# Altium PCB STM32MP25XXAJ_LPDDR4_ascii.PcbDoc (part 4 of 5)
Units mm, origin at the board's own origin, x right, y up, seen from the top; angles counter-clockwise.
Board outline 172 x 137 mm, 4 copper layers (Top Layer, Signal Layer 1, Signal Layer 2, Bottom Layer), stack 1.614 mm thick; 188 components, 294 nets, 1141 pads, 872 vias.
Unrouted connection lines stored in the file: 13.
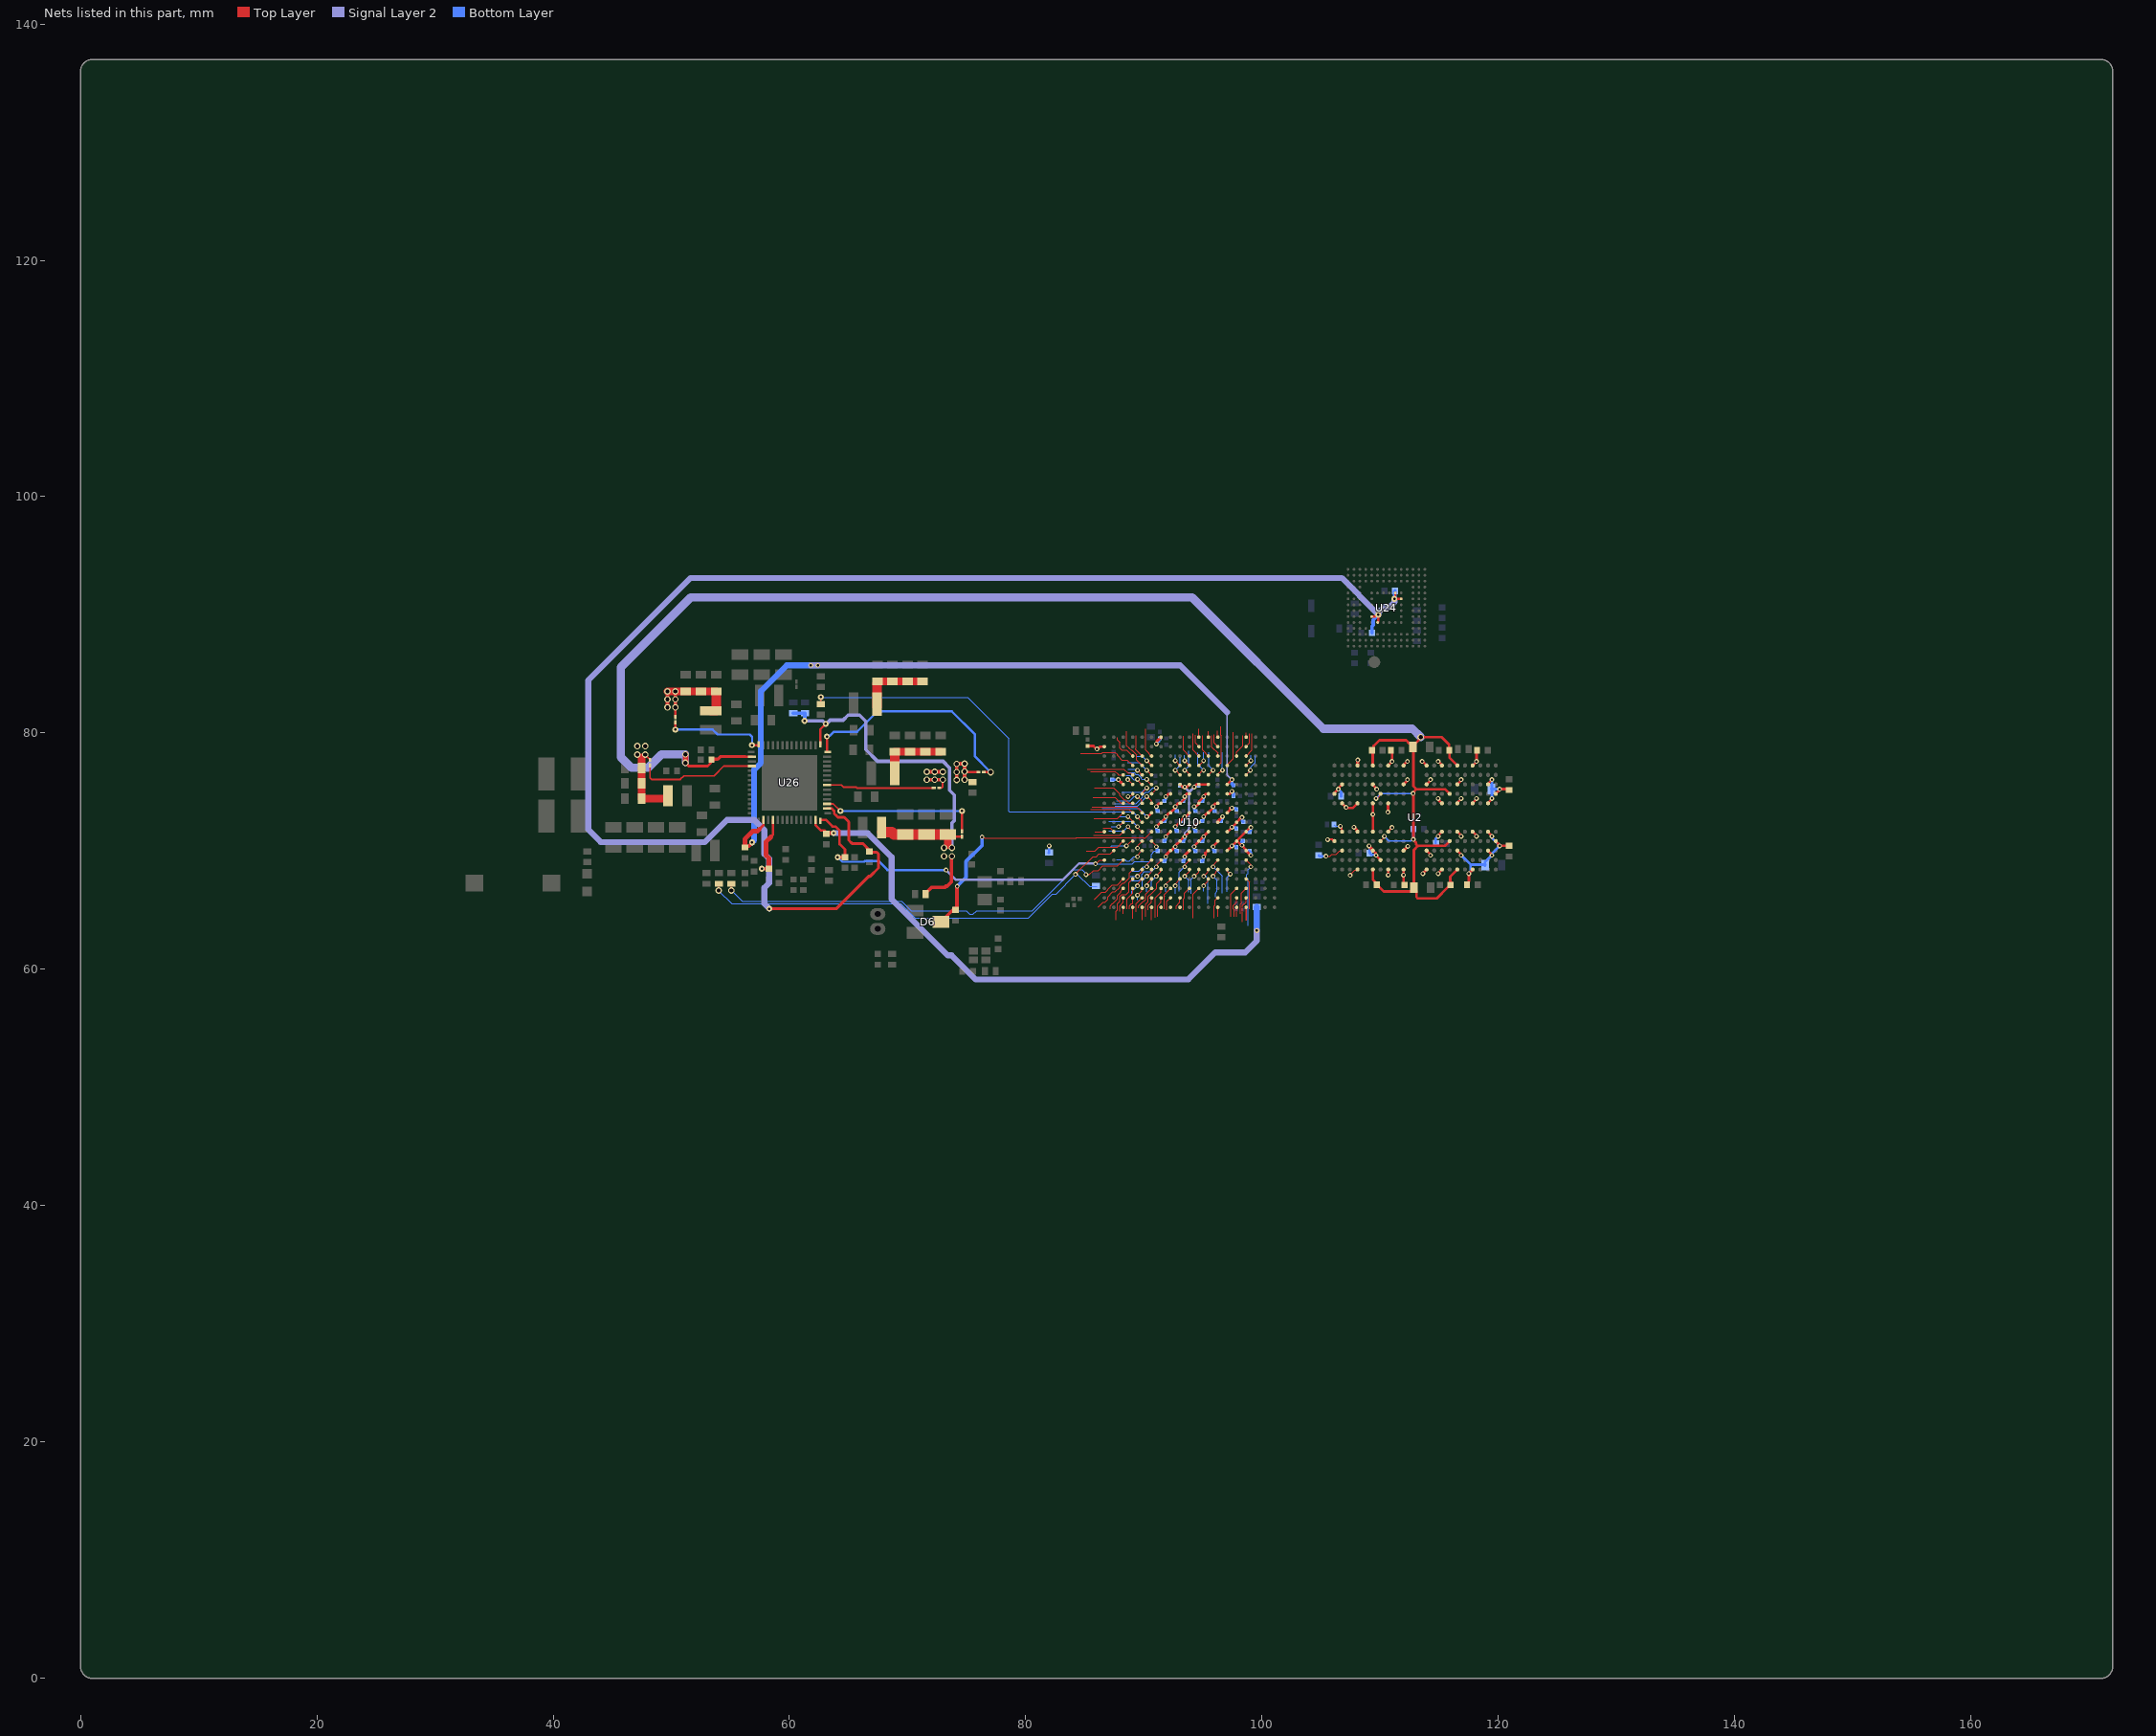
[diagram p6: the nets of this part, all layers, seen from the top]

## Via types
v1: diameter 0.55, hole 0.35, Top Layer to Bottom Layer, 349 vias
v2: diameter 0.4, hole 0.2, Top Layer to Bottom Layer, tented both sides, 257 vias
v3: diameter 0.5, hole 0.2, Top Layer to Bottom Layer, 189 vias
v4: diameter 0.4, hole 0.2, Top Layer to Bottom Layer, 77 vias

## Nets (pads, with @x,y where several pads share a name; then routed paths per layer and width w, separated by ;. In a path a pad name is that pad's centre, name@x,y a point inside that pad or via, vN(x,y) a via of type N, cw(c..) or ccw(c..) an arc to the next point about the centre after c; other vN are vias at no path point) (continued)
PB12: U10.B16 | length 1.2
  Top Layer w0.09: U10.B16@98.65,78.85 98.95,79.15 98.95,79.928
PB13: U10.C15 | length 1.9
  Top Layer w0.09: U10.C15@97.845,78.05 97.845,78.395 98.355,78.905 98.355,79.76
PB14: U10.E16 | length 1.9
  Top Layer w0.1: U10.E16@98.65,76.45 98.65,76.473 99.005,76.828 v2@99.005,76.85
  Bottom Layer w0.1: v2@99.005,76.85 99.062,76.907 99.062,77.157 99.408,77.503 99.408,78.078
  other v2: 99,76.85
PB15: U10.W3 | length 0.6
  Top Layer w0.09: 88.245,64.7 88.245,65.245 U10.W3@88.25,65.25
PC0: U10.P10 | length 2.9
  Top Layer w0.09: v2@93.428,68.775 93.428,68.804 93.845,69.221 U10.P10@93.845,69.25
  Bottom Layer w0.09: 93,66.609 93,68.215 93.45,68.665 v2(93.45,68.675)
PC1: U10.V9 | length 1
  Top Layer w0.09: 92.75,65.128 92.75,65.372 93.045,65.667 U10.V9@93.045,66.05
PC2: U10.V8 | length 1.1
  Top Layer w0.09: 91.945,65.05 91.945,65.75 U10.V8@92.245,66.05
PC3: U10.V5 | length 1.4
  Top Layer w0.09: 89.349,64.884 89.349,65.555 U10.V5@89.845,66.05
PC4: U10.T6 | length 1.1
  Top Layer w0.09: v2@90.283,67.201 90.283,67.242 90.645,67.603 U10.T6@90.645,67.65
  Bottom Layer w0.09: 90.25,66.569 v2(90.25,67.075)
PC5: U10.R7 | length 1.9
  Top Layer w0.09: v2(91.05,67.875) 91.426,68.251 91.426,68.426 U10.R7@91.45,68.45
  Bottom Layer w0.09: 90.633,66.839 90.633,67.453 v2@91.05,67.869
PC6: U10.T7 | length 3.7
  Top Layer w0.09: 90.165,64.471 90.165,65.532 90.344,65.711 90.344,66.17 90.518,66.345 90.562,66.345 91.084,66.867 91.084,67.243 91.445,67.603 U10.T7@91.445,67.65
PC7: U10.U6 | length 2.1
  Top Layer w0.09: 89.555,65.2 89.555,65.372 89.938,65.755 89.972,65.755 90.145,65.928 90.145,66.373 90.623,66.85 U10.U6@90.65,66.85
PC8: U10.V6 | length 1.1
  Top Layer w0.09: 90.355,65.038 90.355,65.389 90.65,65.684 U10.V6@90.65,66.05
PC9: U10.W6 | length 1.1
  Top Layer w0.09: 90.65,64.191 U10.W6@90.65,65.25
PC10: U10.U7 | length 2.7
  Top Layer w0.09: 90.96,64.366 90.96,66.03 91.45,66.521 U10.U7@91.45,66.85
PC11: U10.U5 | length 1.2
  Top Layer w0.09: v4(89.45,66.275) 89.826,66.651 89.826,66.826 U10.U5@89.85,66.85
  Bottom Layer w0.09: 89.448,65.866 89.45,65.868 v4(89.45,66.275)
PC12: U10.V4 | length 1.1
  Top Layer w0.09: 88.755,65.095 88.755,65.372 88.928,65.545 88.997,65.545 89.05,65.598 U10.V4@89.05,66.05
PCIE_CLKINN: U10.W13 | length 0.8
  Top Layer w0.1: 96.25,64.45 U10.W13@96.25,65.25
PCIE_CLKINP: U10.V13 | length 1.8
  Top Layer w0.09: 95.955,64.334 95.955,65.372 96.036,65.453 96.036,65.841 U10.V13@96.245,66.05
PD0: U10.B11 | length 1.1
  Top Layer w0.1: 94.35,79.811 94.35,79.15 U10.B11@94.65,78.85
PD1: U10.A12 | length 0.5
  Top Layer w0.1: U10.A12@95.45,79.65 95.45,80.14
PD2: U10.D9 | length 1
  Top Layer w0.09: v2@92.645,77.65 U10.D9@93.045,77.25
  Bottom Layer w0.09: v2(92.65,77.65) 92.65,78.132
PD3: U10.C10 | length 1.9
  Top Layer w0.1: 93.35,79.731 93.35,78.55 U10.C10@93.85,78.05
PD4: U10.E10 | length 2.4
  Top Layer w0.09: v2@93.475,76.951 93.475,76.882 93.845,76.512 U10.E10@93.845,76.45
  Bottom Layer w0.09: v2(93.45,76.85) 93.795,77.195 93.795,78.463
PD5: U10.D11 | length 1.4
  Top Layer w0.09: U10.D11@94.645,77.25 94.695,77.25 95.095,77.65 v2@95.145,77.65
  Bottom Layer w0.09: v2(95.05,77.65) 95.05,78.343
PD6: U10.E12 | length 2.3
  Top Layer w0.09: U10.E12@95.445,76.45 95.445,76.5 95.5,76.5 95.746,76.746 95.746,76.914 v2@95.805,76.973
  Bottom Layer w0.09: 95.477,78.337 95.477,77.223 v2(95.85,76.85)
PD7: U10.E11 | length 2.4
  Top Layer w0.09: U10.E11@94.645,76.45 94.645,76.501 95.068,76.925 v2@95.068,76.986
  Bottom Layer w0.09: 94.563,78.294 94.563,77.337 v2(95.05,76.85)
PD8: U10.A11 | length 0.7
  Top Layer w0.1: U10.A11@94.65,79.65 94.65,80.355
PD9: U10.E9 | length 2
  Top Layer w0.09: v2@92.645,76.951 92.645,76.903 93.045,76.503 U10.E9@93.045,76.45
  Bottom Layer w0.09: v2(92.65,76.85) 93.076,77.276 93.076,77.961
PD10: U10.C11 | length 2.1
  Top Layer w0.1: 94.15,79.934 94.15,78.55 U10.C11@94.65,78.05
PD11: U10.D10 | length 1
  Top Layer w0.09: v2@93.445,77.65 U10.D10@93.845,77.25
  Bottom Layer w0.09: v2(93.45,77.65) 93.45,78.114
PD12: U10.A16 | length 0.4
  Top Layer w0.09: U10.A16@98.65,79.65 98.65,80.025
PD13: U10.D16 | length 1.1
  Top Layer w0.09: U10.D16@98.65,77.25 v2(99.05,77.65)
  Bottom Layer w0.09: 99.025,78.125 99.05,78.1 v2(99.05,77.65) v2@99.075,77.675
PE0: U10.A13 | length 0.5
  Top Layer w0.09: U10.A13@96.245,79.65 96.245,80.175
PE1: U10.B13 | length 1.1
  Top Layer w0.09: 95.945,79.855 95.945,79.155 U10.B13@96.25,78.85
PE2: U10.C13 | length 1.9
  Top Layer w0.1: 95.75,79.774 95.75,78.802 96.25,78.302 U10.C13@96.25,78.05
PE3: U10.D14 | length 3
  Top Layer w0.09: U10.D14@97.05,77.25 97.05,77.307 97.122,77.379 97.122,77.401 97.555,77.834 97.555,79.859 97.553,79.861 97.553,80.043
PE4: U10.D13 | length 3.5
  Top Layer w0.09: U10.D13@96.245,77.25 96.295,77.25 96.545,77.5 96.545,79.772 96.525,79.792 96.525,80.55
PE5: U10.E13 | length 2.2
  Top Layer w0.09: U10.E13@96.245,76.45 96.245,76.481 96.697,76.934 v2@96.697,76.971
  Bottom Layer w0.09: v2(96.65,76.85) 96.65,78.344
PF0: U10.R10 | length 2.2
  Top Layer w0.09: v2(93.45,67.875) 93.45,67.887 93.82,68.257 93.82,68.42 U10.R10@93.85,68.45
  Bottom Layer w0.09: v2(93.45,67.875) 93.8,67.525 93.8,66.525
PF1: U10.U8 | length 1.9
  Top Layer w0.09: 91.745,65.128 91.745,66.172 91.725,66.192 91.725,66.33 U10.U8@92.245,66.85
PF2: U10.R11 | length 2.3
  Top Layer w0.09: v2(94.245,67.875) 94.258,67.875 94.63,68.247 94.63,68.43 U10.R11@94.65,68.45
  Bottom Layer w0.09: 94,66.4 94,67.63 v2(94.245,67.875)
PF3: U10.T9 | length 1.3
  Top Layer w0.09: v2@92.67,67.198 92.67,67.234 93.045,67.609 U10.T9@93.045,67.65
  Bottom Layer w0.09: 92.655,66.421 v2@92.655,67.07
  other v2: 92.65,67.075
PF4: U10.W5 | length 1.1
  Top Layer w0.09: 89.85,64.191 U10.W5@89.85,65.25
PF5: U10.P7 | length 3.5
  Top Layer w0.09: v2@91.046,68.752 91.046,68.802 91.445,69.2 U10.P7@91.445,69.25
  Bottom Layer w0.09: 88.907,67.49 89.572,67.49 89.814,67.732 89.814,68.035 90.041,68.263 90.638,68.263 v2(91.05,68.675)
PF6: U10.R5 | length 1.4
  Top Layer w0.09: v2(89.45,67.875) 89.826,68.251 89.826,68.431 U10.R5@89.845,68.45
  Bottom Layer w0.09: 88.822,67.875 v2(89.45,67.875)
PF7: U10.R6 | length 1.9
  Top Layer w0.09: v2(90.25,67.875) 90.279,67.875 90.641,68.236 90.641,68.441 U10.R6@90.65,68.45
  Bottom Layer w0.09: 89.875,66.925 89.875,67.488 90.25,67.863 v2(90.25,67.875)
PF8: U10.T5 | length 1.5
  Top Layer w0.09: v2@89.45,67.177 89.45,67.213 89.845,67.608 U10.T5@89.845,67.65
  Bottom Layer w0.09: 88.978,66.362 88.978,66.603 v2(89.45,67.075)
PF9: U10.U4 | length 1.9
  Top Layer w0.09: 88.565,65.125 88.565,65.982 89.05,66.467 U10.U4@89.05,66.85
PF10: U10.P6 | length 2
  Top Layer w0.09: v2@90.245,68.85 U10.P6@90.645,69.25
  Bottom Layer w0.09: 88.93,68.33 89.593,68.33 89.938,68.675 v2(90.25,68.675)
PF11: U10.R4 | length 4.7
  Top Layer w0.09: 86.135,65.29 86.535,65.69 86.707,65.69 86.945,65.928 86.945,66.142 87.358,66.555 87.572,66.555 87.955,66.938 87.955,67.051 88.198,67.294 88.329,67.294 88.765,67.73 88.765,68.165 U10.R4@89.05,68.45
PF12: U10.J5 | length 4.4
  Top Layer w0.1: 85.624,73.75 89.373,73.75 89.845,73.278 U10.J5@89.845,73.25
PF13: U10.G6 | length 4.8
  Top Layer w0.09: U10.G6@90.65,74.85 90.991,75.191 90.991,75.207 91.001,75.218 v2@91.07,75.218
  Bottom Layer w0.09: 87.525,74.03 89.343,74.03 89.905,74.592 89.905,74.768 90.142,75.005 90.393,75.005 90.738,75.35 v2(91.05,75.35)
PF14: U10.F5 | length 1.6
  Top Layer w0.1: v2@89.44,75.968 89.483,75.968 89.802,75.65 U10.F5@89.845,75.65
  Bottom Layer w0.1: 88.487,76.4 88.803,76.4 89.153,76.05 v2@89.45,76.05
  other v2: 89.45,76.075
PF15: U10.G5 | length 3
  Top Layer w0.1: U10.G5@89.85,74.85 89.888,74.888 89.888,74.988 v2(90.25,75.35)
  Bottom Layer w0.1: 88.106,74.984 89.845,74.984 90.211,75.35 v2(90.25,75.35)
PG0: U10.W4 | length 1
  Top Layer w0.09: 89.05,64.282 U10.W4@89.05,65.25
PG1: U10.T3 | length 3.2
  Top Layer w0.09: 85.8,65.922 86.413,66.535 86.752,66.535 86.945,66.728 86.945,66.765 87.253,67.072 87.255,67.072 87.328,67.145 87.745,67.145 U10.T3@88.25,67.65
PG2: U10.T4 | length 4.3
  Top Layer w0.09: 87.643,64.191 87.643,64.912 87.746,65.016 87.746,65.551 87.955,65.76 87.955,66.172 88.128,66.345 88.488,66.345 88.729,66.586 88.729,67.329 U10.T4@89.05,67.65
PG3: U10.U3 | length 2.2
  Top Layer w0.09: 87.166,65.116 87.155,65.128 87.155,65.372 87.328,65.545 87.362,65.545 87.765,65.948 87.765,66.251 88.031,66.517 88.031,66.619 U10.U3@88.215,66.804
PG4: U10.V3 | length 1.3
  Top Layer w0.09: 87.946,64.891 87.946,65.369 88.245,65.667 U10.V3@88.245,66.05
PG5: U10.H3 | length 2.7
  Top Layer w0.09: 85.714,74.549 87.542,74.549 88.034,74.057 88.243,74.057 U10.H3@88.25,74.05
PG6: U10.J3 | length 2.7
  Top Layer w0.09: 85.786,72.75 87.75,72.75 U10.J3@88.25,73.25
PG7: U10.F6 | length 2.4
  Top Layer w0.09: v2@90.239,75.981 90.276,75.981 90.608,75.65 U10.F6@90.645,75.65
  Bottom Layer w0.1: 88.632,76.636 89.169,76.636 89.305,76.5 89.52,76.5 89.8,76.22 89.8,76.134 89.859,76.075 v2(90.25,76.075)
PG8: U10.D4 | length 4.9
  Top Layer w0.1: 84.637,78.268 86.411,78.268 86.498,78.355 87.57,78.355 87.75,78.174 87.75,78.109 88.133,77.726 88.574,77.726 U10.D4@89.05,77.25
PG9: U10.E4 | length 4.1
  Top Layer w0.1: 85.2,76.946 85.389,76.946 85.393,76.95 87.657,76.95 87.661,76.946 88.289,76.946 88.635,76.6 88.9,76.6 U10.E4@89.05,76.45
PG10: U10.E5 | length 1.4
  Top Layer w0.09: v4(89.45,76.85) U10.E5@89.845,76.455
  Bottom Layer w0.09: 88.661,76.922 89.242,76.922 89.255,76.909 89.391,76.909 v4(89.45,76.85)
PG11: U10.E6 | length 2.5
  Top Layer w0.09: v2@90.245,76.85 U10.E6@90.645,76.45
  Bottom Layer w0.09: 88.6,77.5 89.6,77.5 v2(90.25,76.85)
PG12: U10.G4 | length 0.5
  Top Layer w0.1: v4(88.65,74.625) 88.825,74.625 U10.G4@89.05,74.85
PG13: U10.H5 | length 2.7
  Top Layer w0.1: v2(89.45,74.625) 89.825,74.249 89.825,74.075 U10.H5@89.85,74.05
  Bottom Layer w0.1: 87.67,74.275 88.832,74.275 89.168,74.612 89.437,74.612 v2(89.45,74.625)
PG14: U10.E3 | length 2.9
  Top Layer w0.1: 85.476,76.75 87.574,76.75 87.75,76.574 87.75,76.56 87.86,76.45 U10.E3@88.25,76.45
PG15: U10.C6 | length 2.5
  Top Layer w0.1: 90.15,80.336 90.15,78.55 U10.C6@90.65,78.05
PH2: U10.P13 | length 3.2
  Top Layer w0.09: v2@95.845,68.773 95.845,68.809 96.245,69.209 U10.P13@96.245,69.25
  Bottom Layer w0.09: v2(95.85,68.675) 96.623,67.9 96.623,66.462
PH3: U10.T12 | length 1.2
  Top Layer w0.09: v2@95.05,67.079 95.424,67.453 95.424,67.629 U10.T12@95.445,67.65
  Bottom Layer w0.09: 95.05,66.595 v2(95.05,67.075)
PH4: U10.R13 | length 2.7
  Top Layer w0.09: v2(95.85,67.875) 95.85,67.949 96.089,68.188 96.089,68.282 U10.R13@96.25,68.443
  Bottom Layer w0.09: v2@95.854,67.875 95.854,67.871 96.195,67.53 96.195,66.6 96.045,66.449 96.045,66.12
PH5: U10.R14 | length 2.1
  Top Layer w0.1: U10.R14@97.05,68.45 97.05,68.308 v2(97.3,68.058)
  Bottom Layer w0.1: 97.04,66.575 97.04,67.798 v2(97.3,68.058)
PH6: U10.R12 | length 3.4
  Top Layer w0.09: v2(95.05,67.875) 95.41,68.235 95.41,68.41 U10.R12@95.45,68.45
  Bottom Layer w0.09: v2@95.05,67.97 95.124,67.97 95.43,67.665 95.43,67.082 95.429,67.081 95.429,65.552
PH7: U10.U10 | length 2
  Top Layer w0.09: 93.365,65.05 93.365,65.97 93.445,66.05 93.445,66.45 U10.U10@93.845,66.85
PH8: U10.U11 | length 2.7
  Top Layer w0.09: 94.145,64.36 94.145,66.35 U10.U11@94.645,66.85
PH9: U10.T8 | length 1.1
  Top Layer w0.09: v2@91.893,67.187 91.893,67.24 92.245,67.591 U10.T8@92.245,67.65
  Bottom Layer w0.09: 91.85,66.571 v2(91.85,67.075)
PH10: U10.W9
PH11: U10.W8
PH12: U10.V7 | length 1.7
  Top Layer w0.09: 91.15,64.445 91.15,65.372 91.445,65.667 U10.V7@91.445,66.05
PH13: U10.W7
PI0: U10.D6 | length 1.6
  Top Layer w0.1: v2@90.245,77.65 U10.D6@90.645,77.25
  Bottom Layer w0.1: 89.343,78.05 89.85,78.05 v2(90.25,77.65)
PI1: U10.F4 | length 0.6
  Top Layer w0.1: v4(88.632,76.05) 89.057,75.625 U10.F4@89.075,75.625
PI2: U10.J6 | length 4.6
  Top Layer w0.22: v2@90.259,72.838 90.259,72.848 90.645,73.234 U10.J6@90.645,73.25
  Bottom Layer w0.09: 86.463,73.597 89.578,73.597 v2(90.25,72.925)
PI3: U10.H4 | length 3.9
  Top Layer w0.09: 85.8,75.35 87.439,75.35 87.955,74.834 87.955,74.728 88.338,74.345 88.442,74.345 88.507,74.28 88.509,74.28 88.739,74.05 U10.H4@89.05,74.05
PI4: U10.H6 | length 3.8
  Top Layer w0.09: v2(90.25,74.625) 90.28,74.625 90.641,74.264 90.641,74.059 U10.H6@90.65,74.05
  Bottom Layer w0.09: 87.546,73.829 89.454,73.829 v2(90.25,74.625)
PI5: U10.D5 | length 3.5
  Top Layer w0.1: 88.55,80.153 88.55,78.94 88.75,78.74 88.75,78.726 88.923,78.553 88.957,78.553 89.16,78.35 89.174,78.35 89.375,78.149 89.375,77.725 U10.D5@89.85,77.25
PI6: U10.C5 | length 2
  Top Layer w0.1: 89.35,79.774 89.35,78.726 89.304,78.679 89.304,78.596 U10.C5@89.85,78.05
PI7: U10.C4 | length 2.3
  Top Layer w0.1: 87.759,79.601 87.759,79.414 87.95,79.223 87.95,78.726 88.126,78.55 88.55,78.55 U10.C4@89.05,78.05
PI8: U10.N5 | length 2.5
  Top Layer w0.09: v2@89.445,69.65 U10.N5@89.845,70.05
  Bottom Layer w0.09: 87.666,69.285 88.397,69.285 88.502,69.18 88.788,69.18 89.133,69.525 v2(89.45,69.525)
PI9: U10.J4 | length 3.7
  Top Layer w0.1: 85.487,73.55 88.746,73.55 89.046,73.25 U10.J4@89.05,73.25
PI10: U10.C12 | length 1.9
  Top Layer w0.1: 94.95,79.774 94.95,78.55 U10.C12@95.45,78.05
PI11: U10.C16 | length 2.1
  Top Layer w0.09: U10.C16@98.65,78.05 99.15,78.55 99.15,79.925
PMIC_WAKEUPn: R46.1 U10.K5 | length 35.7
  Top Layer w0.1: v2@89.445,72.85 U10.K5@89.845,72.45
  Top Layer w0.15: R46.1@62.65,82.448 v3(62.65,83.033)
  Bottom Layer w0.1: v3@62.703,83.022 75.078,83.022 78.559,79.541 78.559,73.388 78.617,73.33 89.045,73.33 v2(89.45,72.925)
PWR_CPU_ON: R60.1 R272.2 U10.N2 | length 39.6
  Top Layer w0.1: v1@54.014,66.64 54.014,67.229 R60.1@54.03,67.245 ; v4(84.214,68.036) 84.214,68.063 85.687,69.536 85.962,69.536 86.176,69.75 87.15,69.75 U10.N2@87.45,70.05
  Bottom Layer w0.1: v1(54.009,66.67) 55.107,65.572 69.42,65.572 70.634,64.358 78.204,64.358 80.233,64.358 82.263,66.387 82.587,66.387 84.214,68.014 v4(84.214,68.036) 84.38,68.036 85.416,67 R272.2@86,67
PWR_ON: R2.1 U10.P3 | length 36.9
  Top Layer w0.1: v1@55.08,66.64 R2.1@55.08,67.245 ; v4(85.1,68.025) 85.11,68.035 85.385,68.035 85.72,68.37 86.124,68.37 86.504,68.75 87.75,68.75 U10.P3@88.25,69.25
  Bottom Layer w0.1: v1(55.075,66.67) 55.119,66.67 56.017,65.772 69.502,65.772 70.317,64.957 74.948,64.957 75.255,64.65 75.545,64.65 75.853,64.957 80.55,64.957 84.018,68.425 84.775,68.425 v4@85.125,68.075
PZ0: U10.L5 | length 3.1
  Top Layer w0.1: v2@89.445,71.95 89.495,71.95 89.795,71.65 U10.L5@89.845,71.65
  Bottom Layer w0.1: 87.046,72.503 89.022,72.503 v2(89.45,72.075)
PZ1: U10.M3 | length 3.5
  Top Layer w0.09: 85.124,70 85.847,70 86.201,70.354 87.754,70.354 U10.M3@88.25,70.85
PZ2: U10.L3 | length 2.6
  Top Layer w0.09: 85.735,71.354 87.954,71.354 U10.L3@88.25,71.65
PZ3: U10.M5 | length 0.8
  Top Layer w0.1: v4(89.45,70.256) 89.507,70.314 89.507,70.507 U10.M5@89.85,70.85
PZ4: U10.L4 | length 2.3
  Top Layer w0.1: v2@88.648,72.031 88.659,72.031 89.039,71.65 U10.L4@89.045,71.65
  Bottom Layer w0.1: 87.041,71.714 88.289,71.714 v2(88.65,72.075)
PZ5: U10.M4 | length 2.1
  Top Layer w0.1: v2(88.525,70.45) 88.887,70.812 89.006,70.812 U10.M4@89.045,70.85
  Bottom Layer w0.1: 87.179,70.35 87.279,70.45 v2(88.525,70.45)
PZ6: U10.K4 | length 1.4
  Top Layer w0.1: v2(88.65,72.925) 89.05,72.525 U10.K4@89.05,72.45
  Bottom Layer w0.1: 87.9,72.925 v2(88.65,72.925)
PZ7: U10.L2 | length 1
  Top Layer w0.09: 86.536,71.956 87.144,71.956 U10.L2@87.45,71.65
PZ8: U10.K3 | length 1.2
  Top Layer w0.1: v4@87.851,72.06 87.86,72.06 U10.K3@88.25,72.45
  Bottom Layer w0.1: 87.223,72.075 v4(87.851,72.075)
PZ9: U10.L1 | length 0.8
  Top Layer w0.09: 85.875,71.65 U10.L1@86.65,71.65
UCPD1_CC1: U10.P16 | length 5.9
  Top Layer w0.09: U10.P16@98.65,69.25 99.05,68.85 v2(99.05,68.675)
  Bottom Layer w0.1: 98.8,63.713 98.8,67.63 98.7,67.73 98.7,68.02 98.8,68.12 98.8,68.425 v2(99.05,68.675)
UCPD1_CC2: U10.U15 | length 2.6
  Top Layer w0.1: 97.35,64.475 97.35,66.35 U10.U15@97.85,66.85
USB3DR_DM: U10.V16 | length 2.1
  Top Layer w0.1: 98.35,64.038 98.35,65.382 98.645,65.676 U10.V16@98.645,66.05
USB3DR_DP: U10.W16 | length 1.1
  Top Layer w0.11: 98.645,64.15 U10.W16@98.645,65.25
USB3DR_TXRTUNE: U10.T16 | length 2.6
  Top Layer w0.1: U10.T16@98.65,67.65 98.939,67.361 98.939,66.986 98.95,66.974 98.95,65.126
USBH_HS_DM: U10.V15 | length 1.7
  Top Layer w0.1: 97.65,64.48 97.65,65.019 97.55,65.119 97.55,65.404 97.845,65.698 U10.V15@97.845,66.05
USBH_HS_DP: U10.W15 | length 0.8
  Top Layer w0.09: 97.85,64.45 U10.W15@97.85,65.25
USBH_HS_TXRTUNE: U10.U16 | length 2.3
  Top Layer w0.1: 98.15,64.712 98.15,65.511 98.248,65.609 98.248,66.448 U10.U16@98.65,66.85
VBAT: C87.2 D6.3 U10.L6 | length 24
  Top Layer w0.09: v4(76.3,71.2) 76.359,71.141 76.489,71.141 76.508,71.121 84.262,71.121 84.285,71.145 89.972,71.145 89.996,71.121 90.121,71.121 U10.L6@90.65,71.65
  Top Layer w0.3: D6.3@73.2,64.375 72.85,64.025 D6.3@72.825,64.025 73.825,65.025 C87.2@74.05,65.025 ; C87.2@73.925,65.125 74.173,65.125 74.178,65.13 74.178,67.011 v2(74.197,67.03)
  Bottom Layer w0.3: v2(74.197,67.03) 74.952,67.785 74.952,69.133 76.3,70.481 v4(76.3,71.2)
VDD1_DDR: C40.2 C62.2 C63.2 C64.2 C65.2 C66.2 C68.2 C267.2 U2.F1 U2.F12 U2.G4 U2.G9 U2.T4 U2.T9 U2.U1 U2.U12 U26.44 | length 144.9
  Top Layer w0.09: v4(109.65,74.45) 109.7,74.45 109.937,74.687 109.937,74.692 110.025,74.78 U2.G9@110.025,74.85 ; U2.G4@110.025,70.85 110.35,71.176 v4(110.35,71.25)
  Top Layer w0.21: 56.275,78 U26.44@56.83,78
  Top Layer w0.22: U2.F12@109.375,77.25 109.374,78.443 109.35,78.467 109.437,78.554 109.437,78.897 109.925,79.385 112.2,79.385 112.465,79.12 112.59,79.12 C62.2@112.8,78.91 ; U2.F1@109.375,68.45 109.375,67.593 109.605,67.363 109.605,67.29 110.31,66.585 112.64,66.585 C63.2@112.85,66.795 ; v4@112.8,74.882 v2(112.8,71) 112.8,70.951 113.032,70.719 113.032,70.585 113.188,70.429 112.85,70.091 C63.2@112.85,66.92 C63.2@112.85,66.795 ; v4@112.8,74.982 113.064,75.246 ; C63.2@112.85,66.782 C63.2@112.85,66.795 ; C63.2@112.862,66.782 113.06,66.585 113.06,66.128 113.188,65.999 114.772,65.999 115.738,66.965 115.805,66.965 115.921,67.081 C267.2@115.921,67.173 ; 113.17,70.448 115.472,70.448 U2.T4@115.875,70.85 ; U2.T9@115.875,74.85 115.479,75.246 113.064,75.246 ; C267.2@116.066,67.318 C267.2@115.921,67.173 ; U2.U1@116.525,68.45 116.525,68.445 115.921,67.841 C267.2@115.921,67.173 ; U2.U12@116.525,77.256 115.875,77.906 115.875,78.56 115.818,78.616 115.818,79.041 115.21,79.65 v1(113.425,79.65) 113.362,79.587 113.362,79.497 112.985,79.12 112.8,78.935 C62.2@112.8,78.91 ; C62.2@112.8,78.91 112.8,75.51 113.064,75.246
  Top Layer w0.25: v1(51.2,78.198) v1@51.202,78.196 ; v1@51.225,77.473 51.202,77.473 51.475,77.2 53.075,77.2 53.32,77.445 53.32,77.635 53.435,77.75 C40.2@53.505,77.75 ; C40.2@53.51,77.635 53.665,77.79 53.94,77.79 54.15,78 56.275,78
  Top Layer w0.5: v1@51.202,77.473 v1@51.202,78.196
  Signal Layer 2 w0.6: v1@51.2,77.5 v1@51.2,78.223
  Signal Layer 2 w0.7: v1@51.15,78.2 49.178,78.2 48.038,77.06 46.623,77.06 45.738,77.946 45.738,85.572 51.638,91.472 94.083,91.472 105.198,80.357 112.718,80.357 v1(113.425,79.65)
  Bottom Layer w0.09: v4@112.778,74.875 v4(112.778,74.882)
  Bottom Layer w0.12: v4(109.65,74.45) 110.075,74.875 v4@112.778,74.875 ; v4(110.35,71.25) 110.724,70.876 112.592,70.876 v2@112.716,71
  Bottom Layer w0.22: C68.2@112.778,71.922 C68.2@112.8,71.9 ; v2(112.8,71) C68.2@112.8,71.85
  other v1: 51.2,77.473
VDD2_DDR: C41.2 C50.2 C51.2 C52.2 C53.1 C54.1 C55.1 C56.1 C57.1 C58.1 C59.1 C60.1 C61.1 C175.2 C176.2 C195.2 C200.2 C201.2 C202.2 C377.2 C383.2 C386.2 C389.1 L5.2 LNK8.2 R94.2 U2.A4 U2.A9 U2.AA3 U2.AA5 U2.AA8 U2.AA10 U2.AB4 U2.AB9 U2.B3 U2.B5 U2.B8 U2.B10 U2.D1 U2.D5 U2.D8 U2.D12 U2.F3 U2.F5 U2.F8 U2.F10 U2.G2 U2.H1 U2.H5 U2.H8 U2.H12 U2.K1 U2.K3 U2.K10 U2.K12 U2.N1 U2.N3 U2.N10 U2.N12 U2.R1 U2.R5 U2.R8 U2.R12 U2.U3 U2.U5 U2.U8 U2.U10 U2.W1 U2.W5 U2.W8 U2.W12 U10.G14 U10.J14 U10.K15 U10.L14 U10.L16 U10.M15 U10.N14 U10.N16 | length 62.3
  Top Layer w0.09: v2@105.532,69.55 105.731,69.55 105.922,69.74 106.259,69.74 106.546,70.027 106.751,70.027 U2.B3@106.775,70.05 ; v2@107.434,67.975 107.863,68.403 108.028,68.403 U2.D1@108.075,68.45
  Top Layer w0.15: v1(47.798,78.165) 48.2,77.763 LNK8.2@48.2,77.723 ; v2@106.625,72.125 106.625,72.095 106.625,72.057 106.736,71.946 106.736,71.688 U2.B5@106.775,71.65
  Top Layer w0.2: v2(105.55,70.975) 105.579,71.004 105.932,71.004 106.086,70.85 U2.A4@106.125,70.85 ; U2.H5@110.675,71.65 110.675,71.675 v2(111,72)
  Top Layer w0.22: U10.N14@97.05,70.05 v2(97.45,70.45) ; U10.L14@97.05,71.65 97.072,71.65 97.112,71.69 97.118,71.69 v2@97.45,72.022 ; U10.J14@97.05,73.25 97.3,73.5 v4@97.3,73.65 ; U10.G14@97.05,74.85 97.24,74.85 v2(97.45,75.06) ; v2(97.45,72.025) U10.K15@97.85,72.425 ; v2@97.456,70.45 U10.M15@97.85,70.844 ; U10.M15@97.85,70.85 97.872,70.85 97.912,70.81 97.94,70.81 v2@98.16,70.59 ; U10.K15@97.85,72.45 v2@98.25,72.85 ; U10.M15@97.875,70.875 U10.L16@98.65,71.65 98.966,71.966 99.016,71.966 v2(99.05,72) ; v2@98.161,70.59 98.251,70.5 v2(98.3,70.5) 98.3,70.461 98.635,70.126 98.635,70.065 U10.N16@98.65,70.05 v2(99.05,69.65) ; U2.A9@106.14,74.865 U2.A9@106.125,74.85 106.125,74.925 v2(106.45,75.25) ; v2(106.45,75.25) 106.45,75.325 U2.B10@106.775,75.65 U2.B10@106.775,75.645 ; v2(106.62,72.1) v2@106.625,72.095 ; U2.B8@106.775,74.05 106.775,74.025 v2(107.1,73.7) 107.149,73.7 107.184,73.665 107.69,73.665 U2.D8@108.075,74.05 ; v2(107.785,72.031) 108.01,71.804 108.01,71.75 108.075,71.685 U2.D5@108.075,71.65 ; v2@109.05,70.37 109.37,70.05 U2.F3@109.375,70.05 ; v2(109.05,70.45) 109.28,70.22 U2.F3@109.28,70.176 ; U2.F5@109.375,71.65 109.375,72.776 109.387,72.788 109.387,73.098 v2(109.375,73.11) U2.F8@109.375,74.05 ; U2.F10@109.375,75.65 109.375,75.621 109.69,75.305 v2@109.69,75.27 ; U2.F3@109.388,70.068 109.61,69.847 109.61,69.789 109.616,69.783 109.616,69.684 v2(109.65,69.65) ; v2@109.7,69.65 109.696,69.646 109.696,69.579 U2.G2@110.025,69.25 ; v2@110.65,67.96 110.675,67.985 U2.H1@110.675,68.45 ; v2(110.65,73.3) 110.662,73.312 110.662,73.997 U2.H8@110.675,74.01 ; U2.H12@110.675,77.25 111,77.575 111,78.45 C52.2@110.9,78.55 ; v2(111.975,67.97) 111.975,67.21 C54.1@112.05,67.135 ; v2@111.975,67.975 U2.K1@111.975,68.45 ; U2.K3@111.975,70.05 v2(112.325,70.4) ; U2.K10@111.975,75.65 111.98,75.65 112.3,75.97 v2@112.3,75.985 ; U2.K12@111.975,77.25 111.975,77.275 v2(112.3,77.6) ; v2@113.527,77.648 U2.N12@113.925,77.25 ; v2@113.6,68.12 113.925,68.445 U2.N1@113.925,68.45 ; U2.N3@113.925,70.033 114.215,69.743 114.215,69.685 v2(114.25,69.65) ; U2.N10@113.925,75.65 113.93,75.65 v2@114.25,75.97 ; v2@114.9,68.12 115.225,68.445 U2.R1@115.225,68.45 ; v2@114.9,71.32 115.225,71.645 U2.R5@115.225,71.65 ; v2(114.9,74.45) 114.934,74.416 114.934,74.341 U2.R8@115.225,74.05 ; v2(114.9,77.6) 115.225,77.275 U2.R12@115.225,77.25 ; U2.U3@116.525,70.045 116.815,69.754 116.815,69.685 v2(116.85,69.65) ; U2.U5@116.525,71.65 116.85,71.325 v2@116.85,71.32 ; U2.U8@116.525,74.05 116.525,74.085 116.59,74.15 116.59,74.153 116.85,74.413 v2(116.85,74.45) ; U2.U10@116.525,75.65 116.53,75.65 v2@116.85,75.97 ; C55.1@117.35,67.15 117.495,67.295 117.495,67.444 117.5,67.449 v2(117.5,68.1) ; U2.W1@117.725,68.325 v2(117.5,68.1) ; U2.W1@117.825,68.438 U2.W1@117.825,68.445 ; U2.W1@117.825,68.45 U2.W1@117.825,68.445 ; U2.W5@117.825,71.65 117.825,71.645 v2@118.15,71.32 ; U2.W8@117.825,74.07 118.115,74.361 118.115,74.416 v2(118.15,74.45) ; U2.W12@117.825,77.25 118.145,77.57 v2@118.15,77.57 ; v2(118.15,77.6) C53.1@118.15,78.43 ; U2.AA3@119.125,70.05 119.125,70.023 v2@119.4,69.748 ; U2.AA5@119.125,71.65 119.125,71.622 119.45,71.297 v2(119.45,71.25) v2@119.477,71.223 ; U2.AA8@119.125,74.05 119.125,74.084 119.45,74.409 v2(119.45,74.45) ; U2.AA10@119.125,75.65 119.125,75.685 119.45,76.01 v2(119.45,76.05) ; v2@119.4,69.65 v2@119.4,69.748 ; v2@119.4,69.751 v2@119.4,69.748 ; v2(119.45,69.65) 119.45,69.698 v2@119.4,69.748 ; U2.AB4@119.775,70.85 120.015,70.61 120.015,70.522 v2@120.084,70.453 ; U2.AB9@119.775,74.85 120.065,75.141 120.065,75.216 v2(120.1,75.25) 120.82,75.25 C56.1@120.9,75.17 ; v2@120.075,70.425 v2(120.1,70.45) ; v2@120.102,70.448 C57.1@120.886,70.448 ; v2(117.5,68.1) 117.5,68.12 U2.W1@117.825,68.445
  Top Layer w0.28: U2.D12@108.075,77.25 108.087,77.263 108.087,77.712 v2(108.1,77.725)
  Top Layer w0.64: C202.2@47.475,74.425 C202.2@47.475,74.45 ; C200.2@47.475,77.05 C41.2@47.475,75.75 C202.2@47.475,74.45 ; 47.475,77.495 47.475,77.925 ; L5.2@49.725,74.7 49.475,74.45 C202.2@47.475,74.45
  Bottom Layer w0.09: R94.2@106.075,72.25 106.225,72.1 v2(106.62,72.1)
  Bottom Layer w0.22: v2(97.45,70.45) 97.7,70.45 C386.2@97.825,70.325 ; v2(97.45,72.025) 97.7,72.025 C377.2@97.8,71.925 ; v4(97.45,73.65) 97.7,73.65 C201.2@97.825,73.525 ; v2(97.45,75.06) 97.575,74.935 C176.2@97.575,74.675 C176.2@97.575,74.65 ; v2@98.25,70.5 98.25,70.75 C389.1@98.375,70.875 ; v2(98.3,72.85) 98.3,72.575 C175.2@98.4,72.475 ; C195.2@98.925,70.025 99.05,69.9 v2(99.05,69.65) ; C383.2@98.925,71.625 99.05,71.75 v2(99.05,72) ; C61.1@104.8,69.65 104.875,69.575 v2(105.4,69.575) v2@105.425,69.575 ; v2(106.45,75.25) 106.7,75 C60.1@106.7,74.65 C60.1@106.7,74.625 ; v2(109.05,70.45) 109.125,70.375 109.125,69.825 109.266,69.684 109.616,69.684 v2(109.65,69.65) ; C58.1@114.7,70.65 114.7,71.051 v2(114.9,71.25) ; v2(116.85,69.65) 117.65,68.85 ; v2(117.5,68.1) 117.5,68.149 117.65,68.299 117.65,68.85 ; C50.2@118.85,68.775 C50.2@118.85,68.85 ; C50.2@118.9,68.85 C50.2@118.85,68.85 ; C51.2@119.4,75.275 C51.2@119.425,75.25 ; v2(119.45,71.25) 119.45,71.125 120.112,70.463 v2@120.125,70.45 ; v2(119.45,74.45) 119.45,75.225 C51.2@119.425,75.25 ; v2(119.45,76.05) 119.45,75.275 C51.2@119.425,75.25 ; C51.2@119.5,75.25 v2(120.1,75.25) ; v2@120.125,70.475 119.45,69.8 v2(119.45,69.65) 118.85,69.05 C50.2@118.85,68.85 ; 117.65,68.85 C50.2@118.85,68.85
  other v1: 47.123,78.165 47.123,78.89 47.798,78.89
  other v2: 107.45,67.95 110.675,67.97 113.6,68.1 114.9,68.1 116.85,71.25 118.15,71.25 109.7,75.25 112.3,76.05 114.25,76.05 116.85,76.05 111,77.6 113.55,77.6
VDD3V3_USB: C156.2 R197.1 U26.13 | length 49.5
  Top Layer w0.21: U26.13@62.2,72.63 62.2,72.2 62.663,71.737 62.918,71.737 62.92,71.735 62.99,71.735 63.125,71.6 C156.2@63.125,71.53
  Top Layer w0.3: C156.2@63.125,71.53 v3(63.735,71.53)
  Signal Layer 2 w0.5: v3(63.735,71.53) 66.62,71.53 68.65,69.5 68.65,65.93 73.395,61.185 73.717,61.185 75.752,59.15 93.752,59.15 96.035,61.433 98.571,61.433 99.55,62.412 v4(99.55,63.275)
  Bottom Layer w0.5: v4(99.55,63.275) R197.1@99.55,65.275
VDD_DDR_FB: LNK8.1 U26.46 | length 10.2
  Top Layer w0.15: LNK8.1@48.2,77.273 48.2,76.19 48.317,76.073 50.767,76.073 51.067,76.373 51.737,76.373 51.739,76.375 53.627,76.375 54.452,77.2 U26.46@56.83,77.2
VDD_EMMC: C177.2 C180.2 C190.1 U24.E6 U24.F5 U24.J10 U24.K9 U26.16 | length 133.5
  Top Layer w0.18: U24.E6@109.275,89.85 109.58,89.85 109.73,90 v3(109.825,90) ; U24.F5@109.775,89.35 109.775,89.358 109.825,89.408 v3@109.825,89.85 ; v3@111.2,91.25 v3@111.275,91.325 ; U24.J10@111.275,91.85 111.275,91.42 111.267,91.412 111.267,91.333 v3@111.275,91.325 ; U24.K9@111.775,91.35 111.395,91.35 111.362,91.317 111.283,91.317 v3@111.275,91.325
  Top Layer w0.21: U26.16@63.17,73.6 63.6,73.6 63.788,73.412 63.788,73.188 63.934,73.041
  Top Layer w0.25: v3(58.3,65.125) 63.96,65.125 66.7,67.865 66.822,67.865 67.535,68.578 67.535,69.764 67.389,69.91 66.805,69.91 C190.1@66.75,69.965 ; 63.932,73.038 64.098,72.872 64.628,72.872 65.025,72.475 65.025,70.925 65.3,70.65 66.195,70.65 C190.1@66.75,70.095
  Signal Layer 2 w0.5: v3@58.31,65.125 57.882,65.553 57.882,66.908 58.275,67.301 58.275,69.369 57.882,69.762 57.882,71.786 57.019,72.649 54.713,72.649 52.837,70.773 44.034,70.773 42.968,71.839 42.968,84.457 51.626,93.115 106.736,93.115 v3@109.688,90.163 ; v3@109.835,90 109.845,90.01 109.845,90.196 110.269,90.62 110.485,90.62 110.747,90.62 111.21,91.083 v3@111.21,91.25
  Bottom Layer w0.3: C180.2@109.3,88.475 109.3,89.049 109.4,89.149 109.4,89.575 v3(109.825,90) ; v3@111.2,91.25 111.225,91.275 111.225,92 C177.2@111.25,92.025
  other v3: 111.2,91.35
VDD_SDCARD: C142.1 U26.4 | length 5.1
  Top Layer w0.21: 58.425,71.2 58.6,71.375 U26.4@58.6,72.63
  Top Layer w0.3: v3(57.665,68.51) C142.1@58.275,68.51
  Top Layer w0.4: C142.1@58.275,68.51 58.275,69.393 58.01,69.658 58.01,70.785 58.425,71.2
VDDA1V8_AON: C189.2 C393.2 U10.M6 U10.P1 U26.14 | length 36.1
  Top Layer w0.1: v4@85.925,68.925 86.25,69.25 U10.P1@86.65,69.25 ; U10.M6@90.65,70.85 91.025,70.475 v2@91.025,70.375
  Top Layer w0.21: U26.14@62.6,72.63 63.11,72.63 63.648,72.092 63.887,72.092 64.245,71.734 64.245,70.602 64.7,70.147 C189.2@64.7,69.49
  Top Layer w0.3: v3(64.09,69.49) C189.2@64.7,69.49
  Signal Layer 2 w0.2: v2(73.253,68.406) 73.259,68.406 74.065,67.6 83.15,67.6 84.519,68.97 85.689,68.97 85.696,68.963 85.887,68.963 v4@85.925,68.925
  Bottom Layer w0.1: v4@85.925,68.925 85.927,68.927 89.027,68.927 89.205,69.106 90.456,69.106 90.64,69.29 90.64,69.739 90.897,69.995 C393.2@91.104,69.995
  Bottom Layer w0.12: v2(91.05,70.375) v2@91.104,70.321 ; C393.2@91.104,70.071 C393.2@91.175,70
  Bottom Layer w0.2: v3(64.09,69.49) 64.48,69.1 66.321,69.1 66.392,69.171 67.535,69.171 68.3,68.406 v2(73.253,68.406) ; C393.2@91.104,70.071 v2@91.104,70.321
  other v4: 85.9,68.925
VDDCORE: C22.2 C23.2 C24.2 C161.2 C164.1 C166.2 C167.2 C169.2 C173.1 C183.2 C353.2 C355.2 C372.2 C378.2 C390.2 L2.2 LNK2.2 R199.1 U10.A7 U10.B1 U10.F3 U10.G8 U10.G10 U10.H7 U10.H9 U10.J8 U10.J10 U10.K7 U10.K9 | length 24.8
  Top Layer w0.09: v2@91.89,74.475 v2@91.89,74.485
  Top Layer w0.2: C22.2@71.275,84.375 C22.2@71.323,84.423 ; v1@74.87,76.685 LNK2.2@75.98,76.685
  Top Layer w0.22: C353.2@85.225,78.9 85.73,78.9 85.998,78.632 86.088,78.632 86.291,78.835 86.635,78.835 U10.B1@86.65,78.85 ; v4(87.825,76.05) 87.825,76.038 88.044,75.82 88.08,75.82 U10.F3@88.25,75.65 ; v2(91.05,72.075) 91.063,72.075 91.438,72.45 U10.K7@91.445,72.45 ; v2(91.05,73.775) 91.05,73.822 91.252,74.025 91.425,74.025 U10.H7@91.45,74.05 ; v4@91.05,79.056 91.084,79.091 91.084,79.284 U10.A7@91.45,79.65 ; U10.K7@91.458,72.45 91.816,72.807 91.816,72.891 v2(91.85,72.925) 91.85,72.953 92.107,73.21 92.21,73.21 U10.J8@92.25,73.25 92.65,73.65 v2(92.65,73.775) v2@92.65,73.779 ; v2(91.85,74.625) 91.884,74.625 92.094,74.835 92.246,74.835 U10.G8@92.25,74.839 ; v2(92.65,72.075) 92.675,72.075 U10.K9@93.05,72.45 93.05,72.472 93.09,72.512 93.09,72.545 v2@93.45,72.905 ; v2@92.65,73.8 v2@92.65,73.779 ; v2(93.45,72.925) 93.484,72.959 93.56,72.959 U10.J10@93.85,73.25 ; U10.G10@93.845,74.85 93.624,74.85 93.45,74.676 v2(93.45,74.625) 93.45,74.45 U10.H9@93.05,74.05 93.035,74.035 92.906,74.035 v2@92.65,73.779
  Top Layer w0.3: v1@74.151,77.404 v1(74.826,77.404) v1(74.826,76.729) ; v1(74.156,76.024) v1(74.156,76.699) v1(74.156,77.374) ; v1(74.826,76.054) v1(74.826,76.729) ; v1@74.87,76.685 v1(74.826,76.729)
  Top Layer w0.64: C183.2@67.45,84.375 C24.2@68.725,84.375 C23.2@70,84.375 C22.2@71.275,84.375
  Top Layer w0.8: L2.2@67.415,82.2 L2.2@67.415,82.45 C183.2@67.415,84.173
  Bottom Layer w0.2: C161.2@87.325,76.05 v4(87.825,76.05) ; v4(91.05,79.075) 91.275,79.3 91.275,79.475 C355.2@91.35,79.55
  Bottom Layer w0.22: v2(91.05,72.075) 91.05,71.825 C378.2@91.175,71.7 ; v2(91.05,73.775) 91.05,73.55 C173.1@91.175,73.425 ; C169.2@91.725,72.55 91.85,72.675 v2(91.85,72.925) ; C166.2@91.725,74.275 91.85,74.4 v2(91.85,74.625) ; v2(92.65,72.075) 92.65,71.825 C372.2@92.775,71.7 ; v2(92.65,73.775) 92.65,73.525 C167.2@92.775,73.4 ; C164.1@93.325,72.55 93.45,72.675 v2(93.45,72.925) ; C390.2@93.35,74.275 93.45,74.375 v2(93.45,74.625)
  other v4: 86.025,78.65
VDDCORE_FB: LNK2.1 U26.28 | length 19.9
  Top Layer w0.2: U26.28@63.17,78.4 v3(63.17,79.7) ; LNK2.1@76.444,76.687 v1@77.031,76.685
  Bottom Layer w0.2: v3(63.17,79.7) 63.227,79.757 63.401,79.757 63.754,80.111 65.734,80.111 67.457,81.833 73.744,81.833 75.675,79.902 75.675,78.041 v1(77.033,76.683)
VDDCPU: C26.2 C27.2 C28.2 C159.2 C163.2 C168.2 C174.1 C360.1 L3.2 LNK4.1 U10.G12 U10.H11 U10.H13 U10.J12 U10.K13 | length 16.3
  Top Layer w0.2: LNK4.1@50.35,81.35 v1(50.35,82.173)
  Top Layer w0.22: v2(94.25,73.775) 94.284,73.809 94.437,73.809 94.61,73.982 94.61,73.988 94.65,74.028 94.65,74.2 v2@95.075,74.625 ; v2@95.05,72.93 95.355,73.235 95.435,73.235 U10.J12@95.45,73.25 95.875,73.675 v2@95.875,73.697 ; v2(95.05,74.625) 95.05,74.64 95.249,74.839 95.434,74.839 U10.G12@95.445,74.85 ; v2(95.85,73.775) 95.85,73.816 96.055,74.022 96.216,74.022 U10.H13@96.245,74.05 ; U10.K13@96.25,72.45 96.265,72.465 96.265,72.523 v2@96.65,72.907
  Top Layer w0.3: v1(49.675,82.173) v1(49.675,82.848) v1(49.675,83.523) v1(50.35,83.523) v1(50.35,82.848) v1(50.35,82.173)
  Top Layer w0.64: v1(49.675,83.523) 49.675,83.525 C27.2@51.2,83.525 C28.2@52.5,83.525 C26.2@53.8,83.525
  Top Layer w0.8: L3.2@53.35,81.875 53.8,81.875 53.8,83.173
  Bottom Layer w0.22: v2(94.25,73.775) 94.25,73.525 C159.2@94.375,73.4 ; C168.2@94.925,72.525 95.05,72.65 v2(95.05,72.925) ; C360.1@94.925,74.25 95.05,74.375 v2(95.05,74.625) ; v2(95.85,73.775) 95.85,73.525 C174.1@95.975,73.4 ; C163.2@96.5,72.55 96.65,72.7 v2(96.65,72.925)
VDDCPU_FB: LNK4.2 U26.42 | length 8.6
  Top Layer w0.2: v3(50.35,80.29) LNK4.2@50.35,80.9 ; v3(56.825,78.975) U26.42@57.395,78.975
  Bottom Layer w0.2: v3@50.37,80.287 53.499,80.287 53.914,79.872 56.643,79.872 56.845,79.67 v3@56.845,78.972
VDDGPU: C34.2 C35.2 C36.2 C37.2 C191.1 C381.2 C382.2 C388.2 C402.2 L4.2 LNK7.2 U10.K11 U10.L12 U10.M11 U10.M13 U10.N12 | length 14.9
  Top Layer w0.15: LNK7.2@72.675,75.35 72.682,75.358 72.885,75.358 72.973,75.445 v1(72.973,76.038)
  Top Layer w0.2: C35.2@73.05,78.393 C35.2@73.098,78.345
  Top Layer w0.22: v2(94.25,70.375) 94.25,70.45 U10.M11@94.65,70.85 95.025,71.225 v2(95.05,71.225) ; v2@94.27,72.075 U10.K11@94.645,72.45 ; v2(95.05,69.525) 95.2,69.675 95.2,69.844 95.406,70.05 U10.N12@95.445,70.05 ; v2(95.85,70.375) 95.85,70.412 96.245,70.807 U10.M13@96.245,70.85
  Top Layer w0.24: v2@95.05,71.25 U10.L12@95.45,71.65
  Top Layer w0.3: v1(71.623,76.038) v1(72.298,76.038) v1(72.973,76.038) ; v1(71.623,76.713) v1(72.298,76.713) v1(72.973,76.713) ; v2(95.05,71.225) v2@95.05,71.25
  Top Layer w0.64: C37.2@68.9,78.4 C36.2@70.2,78.4 C34.2@71.5,78.4 C35.2@72.8,78.4
  Top Layer w0.8: L4.2@68.925,76.6 68.925,78.073
  Bottom Layer w0.22: v2(94.25,70.375) 94.25,70.125 C381.2@94.375,70 ; v2(94.25,72.075) 94.25,71.825 C388.2@94.375,71.7 C388.2@94.4,71.675 ; C402.2@94.925,69.15 95.05,69.275 v2(95.05,69.525) ; v2(95.85,70.375) 95.85,70.125 C191.1@95.975,70
  Bottom Layer w0.24: C382.2@94.925,70.85 95.05,70.975 v2(95.05,71.225)
  Bottom Layer w0.3: v2@94.2,70.4 v2@94.225,70.4
VDDGPU_FB: LNK7.1 U26.21 | length 9.3
  Top Layer w0.15: U26.21@63.05,75.6 64.383,75.6 64.56,75.423 65.64,75.423 65.713,75.35 LNK7.1@72.225,75.35
VDDIO: C19.2 C143.2 C186.2 C187.2 C192.2 C342.2 C380.2 C387.1 C399.1 C400.2 L6.2 LNK11.2 R27.2 R67.2 R260.2 R261.2 U10.F9 U10.F10 U10.F11 U10.F12 U10.L8 U10.L10 U10.M9 U10.N8 U10.N10 U26.29 | length 54.1
  Top Layer w0.09: U10.L10@93.85,71.65 U10.L10@93.874,71.626
  Top Layer w0.2: U26.29@62.6,79.045 62.6,80.298 v3(63.075,80.773) ; C186.2@73.4,71.4 73.585,71.215 LNK11.2@74.6,71.215 ; v2@93.45,71.227 93.45,71.239 93.838,71.626 U10.L10@93.874,71.626
  Top Layer w0.22: v2@91.844,71.227 91.827,71.244 91.833,71.244 92.239,71.65 U10.L8@92.245,71.65 ; v2(91.85,69.525) 91.85,69.65 U10.N8@92.25,70.05 92.325,70.05 v2(92.65,70.375) 92.698,70.423 92.698,70.498 U10.M9@93.05,70.85 93.425,71.225 v2(93.45,71.225) ; U10.F9@93.05,75.65 93.275,75.425 v2(93.45,75.425) 93.625,75.425 U10.F10@93.837,75.638 ; v2(93.45,69.525) 93.45,69.65 U10.N10@93.85,70.05 ; U10.F10@93.825,75.65 U10.F10@93.837,75.638 ; U10.F10@93.85,75.625 U10.F10@93.837,75.638 ; U10.F10@93.85,75.65 U10.F10@93.837,75.638 ; v2(94.25,75.425) 94.475,75.65 U10.F11@94.647,75.65 ; U10.F11@94.647,75.647 U10.F11@94.647,75.65 ; U10.F11@94.65,75.65 U10.F11@94.647,75.65 ; U10.F12@95.445,75.65 U10.F11@94.647,75.65
  Top Layer w0.3: R67.2@71.525,66.375 71.525,66.44 72.01,66.925 73.125,66.925 73.23,67.03 73.339,67.03 73.712,67.402 73.712,69.52 v1(73.752,69.56) ; v1(73.077,69.56) v1@73.125,69.512
  Top Layer w0.64: 73.4,70.525 C186.2@73.4,70.955
  Top Layer w0.9: L6.2@67.85,71.6 68.65,71.6 68.85,71.4 C187.2@69.8,71.4 C19.2@71.6,71.4 C186.2@73.4,71.4
  Signal Layer 2 w0.15: v2(93.45,71.225) 93.45,71.545 93.826,71.921 93.826,75.049 93.825,75.05
  Signal Layer 2 w0.22: v2(93.45,75.425) 93.825,75.05 93.875,75.05 v2(94.25,75.425)
  Signal Layer 2 w0.3: v3(61.284,81.027) 62.799,81.027 63.05,80.776 v3@63.075,80.776 ; v3(63.075,80.773) 63.129,80.773 63.44,81.084 64.543,81.084 64.973,81.513 65.931,81.513 66.455,80.989 66.455,78.601 67.456,77.6 72.999,77.6 73.551,77.048 73.551,75.156 73.951,74.756 73.951,72.573 73.752,72.375 v1(73.752,70.285)
  Bottom Layer w0.15: C143.2@93.05,75.55 93.125,75.475 v2@93.425,75.475
  Bottom Layer w0.22: R27.2@81.95,69.85 81.975,69.875 R27.2@81.975,69.9 v4(81.975,70.45) ; C399.1@91.725,69.15 91.85,69.275 v2(91.85,69.525) ; C387.1@91.725,70.825 91.85,70.95 v2(91.85,71.225) ; v2(92.65,70.375) 92.65,70.125 C192.2@92.775,70 ; C400.2@93.325,69.15 93.45,69.275 v2(93.45,69.525) ; C380.2@93.325,70.85 93.45,70.975 v2(93.45,71.225) ; v2(94.25,75.425) 94.375,75.55 C342.2@94.625,75.55
  Bottom Layer w0.3: R260.2@60.33,81.68 R261.2@61.305,81.68 61.294,81.669 61.294,81.038 v3(61.284,81.027)
  other v1: 73.077,70.285
VDDIO_FB: LNK11.1 U26.17 | length 13.4
  Top Layer w0.15: U26.17@63.17,74 63.7,74 64.303,73.397 v3(64.315,73.397)
  Top Layer w0.2: LNK11.1@74.6,71.665 v3(74.6,73.4)
  Bottom Layer w0.15: v3(64.315,73.397) v3@74.597,73.397
VDDIO_SDCARD: C217.1 C357.2 U10.F14 U26.2 | length 66.6
  Top Layer w0.21: 57.459,71.873 57.8,72.214 U26.2@57.8,72.63
  Top Layer w0.22: U10.F14@97.05,75.65 v2(97.45,76.05)
  Top Layer w0.3: C217.1@56.225,70.38 56.27,70.425 56.559,70.425 56.835,70.701 v3(56.835,70.737)
  Top Layer w0.4: C217.1@56.225,70.32 56.225,70.38 56.225,71.015 56.899,71.69 57.275,71.69 57.459,71.873
  Signal Layer 2 w0.15: 97.035,81.754 97.035,76.465 v2(97.45,76.05)
  Signal Layer 2 w0.5: v4(61.82,85.726) v4(62.398,85.726) 93.063,85.726 97.035,81.754
  Bottom Layer w0.3: v2(97.45,76.05) 97.45,75.675 C357.2@97.55,75.575
  Bottom Layer w0.5: v3(56.835,70.737) 57.009,70.911 57.009,76.91 57.581,77.482 57.581,81.596 57.575,81.601 57.575,82.099 57.581,82.104 57.581,83.542 59.765,85.726 v4(61.82,85.726) v4(62.398,85.726)
pads on no net: U2.A1 U2.A2 U2.A8 U2.A11 U2.A12 U2.AA1 U2.AA2 U2.AA4 U2.AA9 U2.AA11 U2.AA12 U2.AB1 U2.AB2 U2.AB11 U2.AB12 U2.B1 U2.B12 U2.G11 U2.H3 U2.J5 U2.K5 U2.K8 U2.N5 U2.N8 U2.P2 U2.P4 U2.P5 U2.P8 U2.P9 U2.P11 U2.R2 U2.R3 U2.R4 U2.R9 U2.R10 U2.R11 U2.T2 U2.U2 U2.U4 U2.U9 U2.U11 U2.V2 U2.V3 U2.V4 U2.V9 U2.V10 U2.V11 U2.W3 U2.W10 U2.Y2 U2.Y3 U2.Y4 U2.Y9 U2.Y10 U2.Y11 U10.E19 U10.F19 U10.G17 U10.G19 U10.H17 U10.H19 U10.J18 U10.K17 U10.K18 U10.K19 U10.L18 U10.L19 U10.M18 U10.M19 U10.N18 U10.N19 U10.P17 U10.P18 U10.P19 U10.R18 U10.R19 U24.A1 U24.A2 U24.A7 U24.A8 U24.A9 U24.A10 U24.A11 U24.A12 U24.A13 U24.A14 U24.B1 U24.B7 U24.B8 U24.B9 U24.B10 U24.B11 U24.B12 U24.B13 U24.B14 U24.C1 U24.C3 U24.C5 U24.C7 U24.C8 U24.C9 U24.C10 U24.C11 U24.C12 U24.C13 U24.C14 U24.D1 U24.D2 U24.D3 U24.D4 U24.D12 U24.D13 U24.D14 U24.E1 U24.E2 U24.E3 U24.E5 U24.E8 U24.E9 U24.E10 U24.E12 U24.E13 U24.E14 U24.F1 U24.F2 U24.F3 U24.F10 U24.F12 U24.F13 U24.F14 U24.G1 U24.G2 U24.G3 U24.G10 U24.G12 U24.G13 U24.G14 U24.H1 U24.H2 U24.H3 U24.H12 U24.H13 U24.H14 U24.J1 U24.J2 U24.J3 U24.J12 U24.J13 U24.J14 U24.K1 U24.K2 U24.K3 U24.K6 U24.K7 U24.K10 U24.K12 U24.K13 U24.K14 U24.L1 U24.L2 U24.L3 U24.L12 U24.L13 U24.L14 U24.M1 U24.M2 U24.M3 U24.M7 U24.M8 U24.M9 U24.M10 U24.M11 U24.M12 U24.M13 U24.M14 U24.N1 U24.N3 U24.N6 U24.N7 U24.N8 U24.N9 U24.N10 U24.N11 U24.N12 U24.N13 U24.N14 U24.P1 U24.P2 U24.P7 U24.P8 U24.P9 U24.P10 U24.P11 U24.P12 U24.P13 U24.P14

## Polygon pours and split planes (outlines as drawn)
GND on Signal Layer 2 "GND_L03" (solid, remove dead copper, pour order 152): -0.042,136.898 172,136.898 172,-0.102 -0.042,-0.102
1V8 on Signal Layer 2 "1V8" (solid, pour order 151): 60.675,96.6 60.675,93.472 101.693,93.472 101.748,83.8 116.35,83.8 117.725,85.175 117.725,96.6
5V_STLK on Signal Layer 2 "5V_STLK_L03" (solid, pour order 150): 43.375,82.635 68.35,82.635 68.35,66.229 43.411,66.229
3V3 on Signal Layer 2 "3V3_L03" (solid, remove dead copper, pour order 146): 58,61.394 57.939,61.394 37.983,61.394 35.711,61.394 35.711,67.822 35.711,84.011 44.436,84.011 44.436,73.55 45.447,72.539 58,72.539
VDDIO on Signal Layer 2 "VDDIO_L03" (solid, remove dead copper, pour order 145): 93.617,71.95 93.613,71.945 93.613,69.59 91.403,69.59 89.378,67.564 74.378,67.564 72.553,69.389 72.553,71.646 73.744,72.838 90.259,72.838 91.146,71.95
VDDCORE on Signal Layer 2 "VDDCORE" (solid, remove dead copper, pour order 142): 85.2,78.6 85.925,79.325 91.1,79.325 91.55,78.875 91.542,78.592 93.08,77.054 93.08,75.225 93.657,74.608 93.657,72.016 93.508,71.868 90.93,71.868 89.779,73.018 73.707,73.018 73.707,78.6
VDD2_DDR on Signal Layer 2 "VDD_DDR" (solid, remove dead copper, pour order 144): 107.775,78.3 120.25,78.3 120.25,67.747 100.097,67.755 98.912,68.94 98.476,68.94 97.25,70.174 97.25,75.391 97.25,81.325 94.48,84.095 49.539,84.095 49.219,83.775 49.219,78.471 48.216,77.468 46.918,77.468 46.246,78.14 46.246,85.378 50.853,89.985 96.09,89.985
VDDCPU on Signal Layer 2 "VDDCPU" (solid, remove dead copper, pour order 143): 94.074,72.5 94.074,74.752 93.212,75.614 93.212,76.951 91.618,78.545 81.766,78.735 66.455,78.545 66.455,80.62 66.505,80.67 66.175,81 60.143,81 60.055,80.912 59.116,81.85 49.319,81.85 49.219,81.75 49.219,83.775 50.843,85.4 59.717,85.4 60.603,84.513 60.603,84.5 93.85,84.5 96.931,81.419 96.931,72.5
VDDGPU on Signal Layer 2 "VDDGPU" (solid, remove dead copper, pour order 127): 97.148,69.67 97.148,72.308 94.868,72.308 93.988,72.308 93.666,71.986 93.666,70.788 93.666,69.512 91.192,69.512 89.374,67.715 74.374,67.715 72.549,69.54 72.549,71.782 73.63,72.863 73.63,77.29 68.13,77.29 66.599,75.759 66.599,73.523 68.4,71.766 68.4,66.459 74.813,60.175 93.875,60.175 98.541,64.841 98.541,68.277 97.306,69.512
GND on Top Layer "GND_L01" (solid, pour order 153): 0.178,137.102 0.303,136.977 172,136.977 172,-0.323 0.103,-0.323
VDDCORE on Top Layer "I_SENS_VDDCORE_P" (solid, pour order 134): 72.507,84.74 75.389,81.858 75.389,75.631 75.394,75.626 73.94,75.626 73.395,76.171 73.395,80.872 73.022,81.245 71.375,81.245 67.015,81.245 67.005,84.74
3V3 on Top Layer "3V3" (solid, pour order 137): 44.387,68.548 44.562,68.373 50.91,68.373 52.212,69.675 52.212,70.523 44.588,70.523 44.387,70.323
5V_STLK on Top Layer "5V_STK" (solid, pour order 111): 54.01,75.62 54.667,75.62 54.85,75.803 54.85,75.463 54.367,74.98 54.01,74.98
VDDCPU on Top Layer "I_SENS_VDDCPU_P" (solid, pour order 133): 49.312,83.845 49.312,81.998 49.835,81.475 54.25,81.475 54.245,81.48 54.245,83.845
VDDGPU on Top Layer "I_SENS_VDDGPU_P" (solid, pour order 135): 73.103,75.6 73.245,75.742 73.245,78.72 68.525,78.72 68.525,75.6
VDDIO on Top Layer "VDDIO" (solid, pour order 136): 62.495,78.77 62.495,80.568 63.03,81.103 63.212,81.103 63.65,80.664 63.65,80.123 62.95,79.423 62.95,78.77
NetL6_1 on Top Layer "NetL6_1" (solid, pour order 138): 64.875,73.863 65.338,73.4 66.6,73.4 66.6,71.1 66.598,71.098 65.301,71.098 65.301,72.722 64.875,73.148
GND on Signal Layer 1 "GND_L02" (solid, remove dead copper, pour order 99): -1,138 172,138 172,-1 -1,-1
GND on Bottom Layer "GND_L04" (solid, pour order 155): 0.225,137.075 172,137.075 172,-0.225 0.025,-0.225

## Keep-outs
Keep-Out Layer:
  lines w0.1: 133.661,133.38 142.561,133.38 142.561,135.53 133.661,135.53 133.661,133.38

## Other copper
Top Layer:
  rectangle net VDD2_DDR: 47.155,73.8 50.125,75.6
  text "1" at 134.025,133.811 h2
Signal Layer 1:
  text "2" at 135.309,133.811 h2
Signal Layer 2:
  text "5" at 140.661,133.833 h2
Bottom Layer:
  text "6" at 142.16,133.822 h2

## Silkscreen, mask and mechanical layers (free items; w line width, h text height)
Top Overlay:
  text "VBAT" at 63.012,59.791 h1.2
Top Solder:
  region: 133.736,135.455 133.736,133.455 142.486,133.455 142.486,135.455
Bottom Solder:
  region: 133.736,135.455 133.736,133.455 142.486,133.455 142.486,135.455
M1-Board Shape:
  lines w0.1: 1,137 ccw(c1,136) 0,136 0,95 0,1 ccw(c1,1) 1,0 171,0 ccw(c171,1) 172,1 172,136 ccw(c171,136) 171,137 ; 1,137 1,137 ; 1,137 171,137 ; 171,137 171,137
M2-Board Dimensions:
  lines w0.1: 1,137 ccw(c1,136) 0,136 0,1 ccw(c1,1) 1,0 171,0 ccw(c171,1) 172,1 172,136 ccw(c171,136) 171,137 ; 1,137 1,137 ; 1,137 171,137 ; 171,137 171,137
